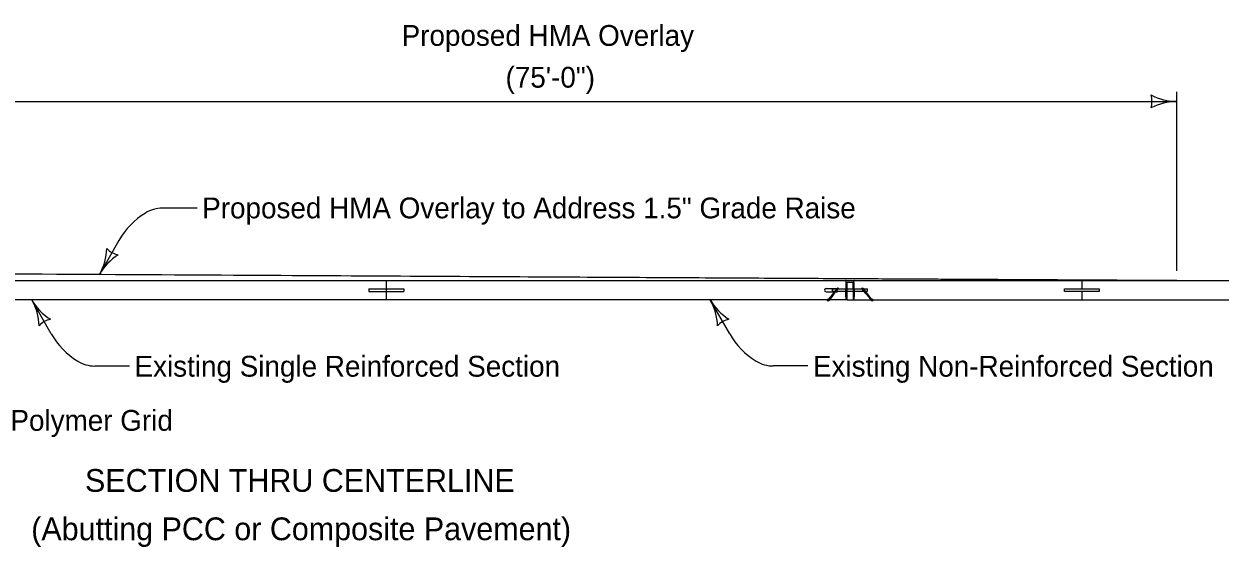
# Model space of a CAD drawing. Extents: x -2135039 to -2124495, y -2139046 to -2132546.
# Drawn here: x -2129936 to -2129016, y -2138011 to -2137609 of the extents above; entities that cross this region are included whole.
import ezdxf

# ---------------------------------------------------------------- set-up
doc = ezdxf.new("R2010")
doc.units = 0
for name, color, linetype in [('BridgeSuperStructureExisting', 7, 'Continuous'), ('Default', 7, 'Continuous'), ('dsnCellElements', 7, 'Continuous'), ('dsnStdLabel', 7, 'Continuous')]:
    doc.layers.add(name, color=color, linetype=linetype)

msp = doc.modelspace()

# ---------------------------------------------------------------- linework, layer by layer
at = {"layer": 'BridgeSuperStructureExisting'}
for p, q in [((-2129802.6, -2137750.38), (-2129829.2, -2137750.38)), ((-2129862.65, -2137775.1), (-2129877.63, -2137801.24)), ((-2130013.55, -2137805.95), (-2129122.54, -2137805.95)), ((-2129657.14, -2137805.95), (-2129657.14, -2137820.8)), ((-2129303.71, -2137816.28), (-2129303.71, -2137806.36)), ((-2129303.71, -2137807.55), (-2129303.12, -2137807.55)), ((-2129303.66, -2137807.55), (-2129303.66, -2137816.28)), ((-2129303.59, -2137807.55), (-2129303.59, -2137816.28)), ((-2129303.54, -2137807.55), (-2129303.54, -2137816.28)), ((-2129303.48, -2137807.55), (-2129303.48, -2137816.28)), ((-2129303.42, -2137807.55), (-2129303.42, -2137816.28)), ((-2129303.36, -2137807.55), (-2129303.36, -2137816.28)), ((-2129303.3, -2137807.55), (-2129303.3, -2137816.28)), ((-2129303.24, -2137807.55), (-2129303.24, -2137816.28)), ((-2129303.18, -2137807.55), (-2129303.18, -2137816.28)), ((-2129303.12, -2137807.55), (-2129303.12, -2137812.48)), ((-2129298.37, -2137807.55), (-2129303.12, -2137807.55)), ((-2129303.12, -2137807.55), (-2129303.12, -2137812.48)), ((-2129298.37, -2137807.55), (-2129298.37, -2137812.48)), ((-2129298.37, -2137812.48), (-2129298.37, -2137807.55)), ((-2129298.37, -2137807.55), (-2129297.77, -2137807.55)), ((-2129298.31, -2137807.55), (-2129298.31, -2137816.28)), ((-2129298.25, -2137807.55), (-2129298.25, -2137816.28)), ((-2129298.19, -2137807.55), (-2129298.19, -2137816.28)), ((-2129298.13, -2137807.55), (-2129298.13, -2137816.28)), ((-2129298.07, -2137807.55), (-2129298.07, -2137816.28)), ((-2129298.01, -2137807.55), (-2129298.01, -2137816.28)), ((-2129297.96, -2137807.55), (-2129297.96, -2137816.28)), ((-2129297.89, -2137807.55), (-2129297.89, -2137816.28)), ((-2129297.84, -2137807.55), (-2129297.84, -2137816.28)), ((-2129297.77, -2137816.28), (-2129297.77, -2137806.36)), ((-2129122.54, -2137805.95), (-2128976.36, -2137805.95)), ((-2129122.54, -2137805.95), (-2129122.54, -2137812.45)), ((-2129670.51, -2137812.45), (-2129643.78, -2137812.45)), ((-2129670.51, -2137812.45), (-2129670.51, -2137814.3)), ((-2129670.51, -2137814.3), (-2129643.78, -2137814.3)), ((-2129643.78, -2137812.45), (-2129643.78, -2137814.3)), ((-2129319.16, -2137812.19), (-2129310.6, -2137812.19)), ((-2129319.16, -2137814.56), (-2129312.59, -2137814.56)), ((-2129314.03, -2137816.28), (-2129315.78, -2137818.38)), ((-2129313.1, -2137816.28), (-2129314.86, -2137818.38)), ((-2129314.11, -2137814.26), (-2129314.11, -2137812.48)), ((-2129314.11, -2137812.48), (-2129310.84, -2137812.48)), ((-2129314.11, -2137814.26), (-2129312.34, -2137814.26)), ((-2129310.35, -2137811.9), (-2129314.03, -2137816.28)), ((-2129313.1, -2137816.28), (-2129309.8, -2137812.36)), ((-2129311.66, -2137814.56), (-2129310.25, -2137814.56)), ((-2129311.41, -2137814.26), (-2129304.07, -2137814.26)), ((-2129310.84, -2137812.48), (-2129310.84, -2137812.48)), ((-2129310.25, -2137814.26), (-2129310.25, -2137814.56)), ((-2129309.92, -2137812.48), (-2129304.07, -2137812.48)), ((-2129304.07, -2137818.42), (-2129304.07, -2137812.48)), ((-2129303.9, -2137812.3), (-2129303.9, -2137812.3)), ((-2129303.71, -2137818.38), (-2129303.71, -2137816.28)), ((-2129303.66, -2137816.28), (-2129303.66, -2137818.38)), ((-2129303.59, -2137816.28), (-2129303.59, -2137818.38)), ((-2129303.54, -2137816.28), (-2129303.54, -2137818.38)), ((-2129303.48, -2137816.28), (-2129303.48, -2137818.38)), ((-2129303.42, -2137816.28), (-2129303.42, -2137818.38)), ((-2129303.36, -2137816.28), (-2129303.36, -2137818.38)), ((-2129303.3, -2137816.28), (-2129303.3, -2137818.38)), ((-2129303.24, -2137816.28), (-2129303.24, -2137818.38)), ((-2129303.18, -2137816.28), (-2129303.18, -2137818.38)), ((-2129303.12, -2137812.48), (-2129303.12, -2137814.26)), ((-2129303.12, -2137812.48), (-2129298.37, -2137812.48)), ((-2129303.12, -2137814.26), (-2129298.37, -2137814.26)), ((-2129303.12, -2137814.26), (-2129303.12, -2137816.28)), ((-2129303.12, -2137816.28), (-2129303.12, -2137818.38)), ((-2129298.37, -2137812.48), (-2129298.37, -2137814.26)), ((-2129298.37, -2137814.26), (-2129298.37, -2137816.28)), ((-2129298.37, -2137816.28), (-2129298.37, -2137818.38)), ((-2129298.31, -2137816.28), (-2129298.31, -2137818.38)), ((-2129298.25, -2137816.28), (-2129298.25, -2137818.38)), ((-2129298.19, -2137816.28), (-2129298.19, -2137818.38)), ((-2129298.13, -2137816.28), (-2129298.13, -2137818.38)), ((-2129298.07, -2137816.28), (-2129298.07, -2137818.38)), ((-2129298.01, -2137816.28), (-2129298.01, -2137818.38)), ((-2129297.96, -2137816.28), (-2129297.96, -2137818.38)), ((-2129297.89, -2137816.28), (-2129297.89, -2137818.38)), ((-2129297.84, -2137816.28), (-2129297.84, -2137818.38)), ((-2129297.77, -2137818.38), (-2129297.77, -2137816.28)), ((-2129297.42, -2137818.42), (-2129297.42, -2137812.48)), ((-2129297.42, -2137812.48), (-2129291.58, -2137812.48)), ((-2129297.42, -2137812.72), (-2129297.42, -2137812.72)), ((-2129297.42, -2137814.26), (-2129290.08, -2137814.26)), ((-2129288.39, -2137816.28), (-2129291.68, -2137812.36)), ((-2129291.14, -2137811.9), (-2129287.46, -2137816.28)), ((-2129290.65, -2137812.48), (-2129290.65, -2137812.48)), ((-2129290.65, -2137812.48), (-2129287.38, -2137812.48)), ((-2129289.15, -2137814.26), (-2129287.38, -2137814.26)), ((-2129288.39, -2137816.28), (-2129286.63, -2137818.38)), ((-2129287.46, -2137816.28), (-2129285.7, -2137818.38)), ((-2129287.38, -2137814.26), (-2129287.38, -2137812.48)), ((-2129135.91, -2137814.3), (-2129135.91, -2137812.45)), ((-2129135.91, -2137812.45), (-2129109.18, -2137812.45)), ((-2129109.18, -2137814.3), (-2129135.91, -2137814.3)), ((-2129122.54, -2137814.3), (-2129122.54, -2137820.8)), ((-2129109.18, -2137812.45), (-2129109.18, -2137814.3)), ((-2129881.59, -2137820.79), (-2130459.04, -2137820.79)), ((-2129317.82, -2137820.8), (-2130459.04, -2137820.8)), ((-2129914.67, -2137846.94), (-2129929.64, -2137820.81)), ((-2129393.22, -2137846.93), (-2129408.2, -2137820.8)), ((-2129315.78, -2137818.38), (-2129318.2, -2137821.25)), ((-2129317.65, -2137821.71), (-2129318.2, -2137821.25)), ((-2129303.71, -2137820.8), (-2129317.82, -2137820.8)), ((-2129314.86, -2137818.38), (-2129317.65, -2137821.71)), ((-2129304.07, -2137818.42), (-2129304.07, -2137818.42)), ((-2129303.71, -2137820.8), (-2129303.71, -2137818.38)), ((-2129303.66, -2137818.38), (-2129303.66, -2137820.8)), ((-2129303.59, -2137818.38), (-2129303.59, -2137820.8)), ((-2129303.54, -2137818.38), (-2129303.54, -2137820.8)), ((-2129303.48, -2137818.38), (-2129303.48, -2137820.8)), ((-2129303.42, -2137818.38), (-2129303.42, -2137820.8)), ((-2129303.36, -2137818.38), (-2129303.36, -2137820.8)), ((-2129303.3, -2137818.38), (-2129303.3, -2137820.8)), ((-2129303.24, -2137818.38), (-2129303.24, -2137820.8)), ((-2129303.18, -2137818.38), (-2129303.18, -2137820.8)), ((-2129303.12, -2137818.38), (-2129303.12, -2137820.8)), ((-2129303.12, -2137820.8), (-2129298.37, -2137820.8)), ((-2129298.37, -2137818.38), (-2129298.37, -2137820.8)), ((-2129298.37, -2137820.8), (-2129122.54, -2137820.8)), ((-2129298.31, -2137818.38), (-2129298.31, -2137820.8)), ((-2129298.25, -2137818.38), (-2129298.25, -2137820.8)), ((-2129298.19, -2137818.38), (-2129298.19, -2137820.8)), ((-2129298.13, -2137818.38), (-2129298.13, -2137820.8)), ((-2129298.07, -2137818.38), (-2129298.07, -2137820.8)), ((-2129298.01, -2137818.38), (-2129298.01, -2137820.8)), ((-2129297.96, -2137818.38), (-2129297.96, -2137820.8)), ((-2129297.89, -2137818.38), (-2129297.89, -2137820.8)), ((-2129297.84, -2137818.38), (-2129297.84, -2137820.8)), ((-2129297.77, -2137820.8), (-2129297.77, -2137818.38)), ((-2129286.63, -2137818.38), (-2129283.83, -2137821.71)), ((-2129285.7, -2137818.38), (-2129283.29, -2137821.25)), ((-2129283.83, -2137821.71), (-2129283.29, -2137821.25)), ((-2129122.54, -2137820.8), (-2128976.36, -2137820.8)), ((-2129854.62, -2137871.67), (-2129881.22, -2137871.67)), ((-2129333.17, -2137871.66), (-2129359.77, -2137871.66))]:
    msp.add_line(p, q, dxfattribs=at)
for points in [[(-2129303.12, -2137807.6), (-2129303.07, -2137807.55)], [(-2129303.12, -2137814.36), (-2129303.02, -2137814.26)]]:
    msp.add_lwpolyline(points, dxfattribs=at)
for centre in [(-2129313.09, -2137814.8), (-2129288.64, -2137814.5), (-2129317.93, -2137820.56), (-2129283.56, -2137820.56)]:
    msp.add_circle(centre, 0.238, dxfattribs=at)
for centre, radius, start, end in [((-2129829.2, -2137775.38), 25, 90, 121.71831), ((-2129811.12, -2137804.64), 59.4, 121.71831, 150.17827), ((-2129914.72, -2137779.98), 42.75, 330.17945, 358.25194), ((-2129840.54, -2137822.5), 42.75, 122.10696, 150.17945), ((-2129859.81, -2137770.14), 16.51, 222.4461, 257.9128), ((-2129304.13, -2137806.36), 0.416, 0, 90), ((-2129297.36, -2137806.36), 0.416, 90, 180), ((-2129319.16, -2137813.37), 1.19, 90, 270), ((-2129310.08, -2137812.13), 0.356, 320.00367, 139.99636), ((-2129303.89, -2137812.48), 0.178, 0, 180), ((-2129303.89, -2137812.48), 0.178, 0, 180), ((-2129297.59, -2137812.48), 0.178, 0, 180), ((-2129291.41, -2137812.13), 0.356, 40.00364, 219.99633), ((-2129892.56, -2137799.55), 42.75, 209.82055, 237.89304), ((-2129966.73, -2137842.07), 42.75, 1.74806, 29.82055), ((-2129371.11, -2137799.54), 42.75, 209.82055, 237.89304), ((-2129445.29, -2137842.06), 42.75, 1.74806, 29.82055), ((-2129303.89, -2137818.42), 0.178, 180, 0), ((-2129297.59, -2137818.42), 0.178, 180, 0), ((-2129911.82, -2137851.91), 16.51, 102.0872, 137.5539), ((-2129390.38, -2137851.9), 16.51, 102.0872, 137.5539), ((-2129863.13, -2137817.4), 59.4, 209.82173, 238.28169), ((-2129341.69, -2137817.4), 59.4, 209.82173, 238.28169), ((-2129881.22, -2137846.67), 25, 238.28169, 270), ((-2129359.77, -2137846.66), 25, 238.28169, 270)]:
    msp.add_arc(centre, radius, start, end, dxfattribs=at)
for points in [[(-2129297.42, -2137812.6), (-2129297.39, -2137812.61), (-2129297.36, -2137812.6), (-2129297.33, -2137812.6), (-2129297.31, -2137812.6), (-2129297.29, -2137812.61), (-2129297.28, -2137812.6)], [(-2129297.42, -2137812.72), (-2129297.39, -2137812.72), (-2129297.36, -2137812.72), (-2129297.33, -2137812.72), (-2129297.31, -2137812.72), (-2129297.29, -2137812.72), (-2129297.28, -2137812.72)], [(-2129297.42, -2137812.84), (-2129297.39, -2137812.84), (-2129297.36, -2137812.84), (-2129297.33, -2137812.84), (-2129297.31, -2137812.84), (-2129297.29, -2137812.84), (-2129297.28, -2137812.84)], [(-2129297.42, -2137812.96), (-2129297.39, -2137812.96), (-2129297.36, -2137812.96), (-2129297.33, -2137812.96), (-2129297.31, -2137812.96), (-2129297.29, -2137812.96), (-2129297.28, -2137812.96)], [(-2129297.42, -2137813.08), (-2129297.39, -2137813.08), (-2129297.36, -2137813.08), (-2129297.33, -2137813.08), (-2129297.31, -2137813.08), (-2129297.29, -2137813.08), (-2129297.28, -2137813.08)], [(-2129297.42, -2137813.2), (-2129297.39, -2137813.2), (-2129297.36, -2137813.2), (-2129297.33, -2137813.2), (-2129297.31, -2137813.2), (-2129297.29, -2137813.2), (-2129297.28, -2137813.2)], [(-2129297.42, -2137813.31), (-2129297.39, -2137813.32), (-2129297.36, -2137813.31), (-2129297.33, -2137813.31), (-2129297.31, -2137813.31), (-2129297.29, -2137813.32), (-2129297.28, -2137813.31)], [(-2129297.42, -2137813.43), (-2129297.39, -2137813.44), (-2129297.36, -2137813.43), (-2129297.33, -2137813.43), (-2129297.31, -2137813.43), (-2129297.29, -2137813.44), (-2129297.28, -2137813.43)], [(-2129297.42, -2137813.55), (-2129297.39, -2137813.56), (-2129297.36, -2137813.55), (-2129297.33, -2137813.55), (-2129297.31, -2137813.55), (-2129297.29, -2137813.56), (-2129297.28, -2137813.55)], [(-2129297.42, -2137813.67), (-2129297.39, -2137813.68), (-2129297.36, -2137813.67), (-2129297.33, -2137813.67), (-2129297.31, -2137813.67), (-2129297.29, -2137813.68), (-2129297.28, -2137813.67)], [(-2129297.42, -2137813.79), (-2129297.39, -2137813.79), (-2129297.36, -2137813.79), (-2129297.33, -2137813.79), (-2129297.31, -2137813.79), (-2129297.29, -2137813.79), (-2129297.28, -2137813.79)], [(-2129297.42, -2137813.91), (-2129297.39, -2137813.91), (-2129297.36, -2137813.91), (-2129297.33, -2137813.91), (-2129297.31, -2137813.91), (-2129297.29, -2137813.91), (-2129297.28, -2137813.91)], [(-2129297.42, -2137814.03), (-2129297.39, -2137814.03), (-2129297.36, -2137814.03), (-2129297.33, -2137814.03), (-2129297.31, -2137814.03), (-2129297.29, -2137814.03), (-2129297.28, -2137814.03)], [(-2129297.42, -2137814.15), (-2129297.39, -2137814.15), (-2129297.36, -2137814.15), (-2129297.33, -2137814.15), (-2129297.31, -2137814.15), (-2129297.29, -2137814.15), (-2129297.28, -2137814.15)]]:
    msp.add_spline(points, degree=3, dxfattribs=at)
at = {"layer": 'Default'}
msp.add_line((-2130013.55, -2137800.46), (-2129049.45, -2137805.95), dxfattribs=at)
at = {"layer": 'dsnCellElements'}
for centre, radius, start, end in [((-2129085.07, -2137668.31), 16.42, 342.26665, 17.73335), ((-2129049.44, -2137625.81), 42.5, 241.92751, 270), ((-2129049.44, -2137710.81), 42.5, 90, 118.07249)]:
    msp.add_arc(centre, radius, start, end, dxfattribs=at)
at = {"layer": 'dsnStdLabel'}
for p, q in [((-2129049.45, -2137798.51), (-2129049.45, -2137660.88)), ((-2130013.55, -2137668.31), (-2129049.45, -2137668.31))]:
    msp.add_line(p, q, dxfattribs=at)
msp.add_lwpolyline([(-2129049.45, -2137805.95), (-2130013.55, -2137800.46), (-2130013.55, -2137805.93), (-2130013.55, -2137805.94), (-2130013.55, -2137805.95)], close=True, dxfattribs=at)

# ---------------------------------------------------------------- texts
at = {"layer": 'BridgeSuperStructureExisting'}
msp.add_text('SECTION THRU CENTERLINE', height=17.5, dxfattribs=at).set_placement((-2129888.73, -2137968.39))
at = {"layer": 'dsnStdLabel'}
for s, height, p in [('Proposed HMA Overlay', 16, (-2129645.38, -2137625.58)), ('(75\'-0")', 16, (-2129565.51, -2137657.72)), ('Proposed HMA Overlay to Address 1.5" Grade Raise', 16, (-2129798.65, -2137758.18)), ('Existing Single Reinforced Section', 16, (-2129850.67, -2137879.87)), ('Existing Non-Reinforced Section', 16, (-2129329.22, -2137879.86)), ('Polymer Grid', 16, (-2129946.04, -2137921.47)), ('(Abutting PCC or Composite Pavement)', 17.5, (-2129930.04, -2138005.57))]:
    msp.add_text(s, height=height, dxfattribs=at).set_placement(p)

doc.saveas('drawing.dxf')
